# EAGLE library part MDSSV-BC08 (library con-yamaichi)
YAMAICHI CONNECTOR
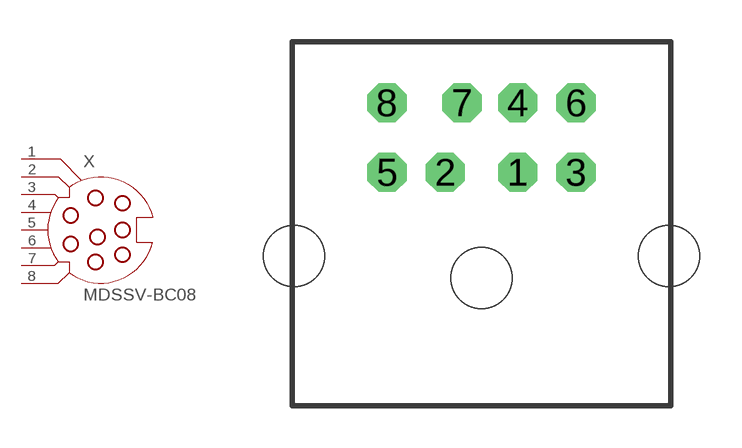
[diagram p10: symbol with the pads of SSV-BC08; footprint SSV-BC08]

Designator prefix X

## MDSSV-BC08 (OC_FARNELL: unknown; OC_NEWARK: unknown)  [SSV-BC08]
1  1  pas
2  2  pas
3  3  pas
4  4  pas
5  5  pas
6  6  pas
7  7  pas
8  8  pas

## Footprint SSV-BC08 (pad centres in mm)
Mini Din YAMAICHI CONNECTOR
drill 0.9 octagon: 1 1.3,8.5; 2 -1.3,8.5; 3 3.4,8.5; 4 1.3,11; 5 -3.4,8.5; 6 3.4,11; 7 -0.7,11; 8 -3.4,11
hole 2.2 at -6.75,5.5
hole 2.2 at 0,4.7
hole 2.2 at 6.75,5.5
